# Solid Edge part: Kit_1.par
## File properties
Sűrűség: 0,000 kg/m^3
Pontosság: 0,990
Author: bmolnar
Last saved by: ahadarics
Revision: 77
Username: bmolnar
Dokumentum tartalom típus: 0
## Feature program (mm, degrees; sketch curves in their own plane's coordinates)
base feature "unnamed BaseFeature 1"
sketch for "unnamed Hole 1" plane through (0, 0, 99) normal (0, 0, 1) x-axis (0, 1, 0)
  hole centre (-28.25, 28.25) bore radius 3.3235
hole "unnamed Hole 1" through
sketch for "unnamed Hole 2" plane through (0, 0, 99) normal (0, 0, 1) x-axis (0, 1, 0)
  hole centre (28.25, 28.25) bore radius 3.3235
hole "unnamed Hole 2" through
sketch for "unnamed Hole 3" plane through (0, 0, 99) normal (0, 0, 1) x-axis (0, 1, 0)
  hole centre (28.25, -28.25) bore radius 3.3235
hole "unnamed Hole 3" through
sketch for "unnamed Hole 4" plane through (0, 0, 99) normal (0, 0, 1) x-axis (0, 1, 0)
  hole centre (-28.25, -28.25) bore radius 3.3235
hole "unnamed Hole 4" through
pattern "unnamed Pattern 1" of "unnamed Hole 1", "unnamed Hole 2", "unnamed Hole 3", "unnamed Hole 4"
sketch for "Furat_5" plane through (-38.44, 0, 92.125) normal (-0.999962, 0, 0.008727) x-axis (0, 1, 0)
  hole centre (-0.0002, 0.6247) bore radius 4.283
hole "Furat_5" diameter 8.566 finite
thread "unnamed Thread 1"
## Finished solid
Body 1: solid body, 308 faces, 756 edges, 463 vertices.
  Faces by surface: plane 141, cylinder 75, swept 61, cone 20, torus 10, spline 1
  Edges by curve: line 431, circle 154, spline 126, ellipse 30, curve on surface 15
Bounding box of the edges (mm; curved faces can reach further): 77.000 x 77.000 x 13.750, from (-38.5, -38.5, 85.25) to (38.5, 38.5, 99).
Cylindrical faces by radius (mm): R0.2 x48, R0.2008 x2, R0.2009 x2, R0.402 x1, R0.4899 x1, R3.3235 x4, R4.283 x1, R4.9 x4, R5.15 x4, R5.25 x4, R8.27 x1, R8.85 x1, R9 x1, R10.25 x1
Conical faces (half-angle, radius in mm at the cone's reference point): 0.5 deg R12 x4, 0.5 deg R13.5 x2, 7 deg R9.5925 x1, 14 deg R8.135 x1, 14 deg R8.4811 x1, 17 deg R8.135 x1, 23 deg R8.829 x1, 42.5 deg R8.1233 x1, 45 deg R3.32 x4, 45 deg R9 x1, 84 deg R8.4608 x1, 85 deg R9.9462 x1, 87 deg R8.1765 x1
Toroidal faces (ring radius, tube radius in mm): R4.7 r0.2 x8, R8.8057 r0.2025 x1, R9.2522 r0.2925 x1
Planar faces by outward normal: +x 12, +y 13, +z 19, -x 14, -y 14, -z 1, oblique 68
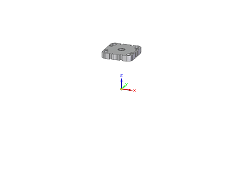
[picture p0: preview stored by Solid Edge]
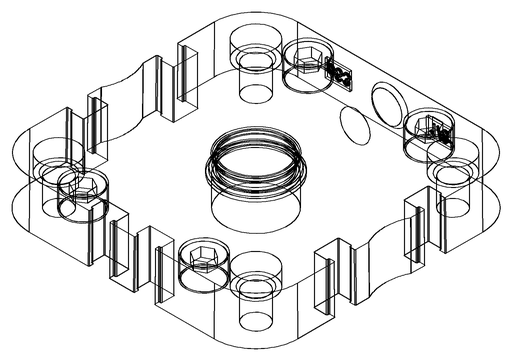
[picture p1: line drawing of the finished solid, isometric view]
